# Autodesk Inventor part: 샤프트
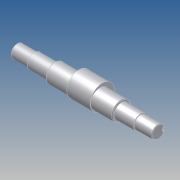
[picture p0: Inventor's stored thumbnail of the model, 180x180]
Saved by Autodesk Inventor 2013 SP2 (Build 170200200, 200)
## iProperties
Created: 2013-06
Part Number: 샤프트
Document SubType Name: Modeling
Designer: SeoGD™[esajin.kr]
Density: 1 g/cm^3
Material: 일반
Mass: 168.947 g
Surface Area: 248.524 cm^2
Volume: 168.947 cm^3
Author: SeoGD™[esajin.kr]
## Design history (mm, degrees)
sketch "스케치1"
  geometry: L1 (-20.5, -41.331)-(-20.5, 32.669) reference; L2 (7.5, -30.031)-(7.5, 21.369) reference; L3 (135.5, -30.331)-(135.5, 21.669) reference; L4 (121.5, 21.369)-(121.5, -30.031) reference; L5 (184.5, -4.331)-(-57.5, -4.331); L6 (184.5, -4.331)-(184.5, 6.669); L7 (154.5, 8.169)-(121.5, 8.169); L8 (121.5, 8.169)-(121.5, 11.669); L9 (121.5, 11.669)-(7.5, 11.669); L10 (7.5, 11.669)-(7.5, 8.169); L11 (7.5, 8.169)-(-27.5, 8.169); L12 (-27.5, 8.169)-(-27.5, 6.669); L13 (-27.5, 6.669)-(-57.5, 6.669); L14 (-57.5, 6.669)-(-57.5, -4.331); L15 (154.5, 8.169)-(154.5, 6.669); L16 (154.5, 6.669)-(184.5, 6.669); C1 r 32.5 at (64.5, -4.331) reference; 1 further point
  constraints: 24 end point, 8 perpendicular, 5 point on line, 3 parallel, 2 collinear
  dimensions: "d1" = 25 diameter of L11 L5; "d2" = 32 diameter of L9 L5; "d3" = 22 diameter of L13 L5; "d4" = 35 distance of L10.end L11.end; "d5" = 30 distance of L12.end L13.end; "d15" = 33 distance of L7.start L7.end; "d26" = 30 distance of L15.end L6.end
revolve "회전1" sketch "스케치1" stored, may be unused: angle "d6" = 90 deg
node "작업 평면1"
sketch "스케치2"
  geometry: C1 r 16 at (0, 0) reference; C2 r 16 at (0, 0) reference; C3 r 20.75 at (0, 4); C4 r 16 at (0, 0) reference; 1 further point
  constraints: 1 centre point, 1 vertical alignment
  dimensions: "d8" = 41.5 diameter of C3; "d25" = 4 distance of C3.centre C1.centre
extrude "돌출1" join sketch "스케치2" stored distance "d9" = 40; taper "d10" = 0 deg
chamfer "모따기1" distance "d11" = 1; stored, may be unused: second distance "d12" = 2, angle "d13" = 45 deg
node "작업 평면2"
sketch "스케치3"
  geometry: L1 (-15, -10)-(-15, 10) reference; L2 (-15, 3)-(0, 3); L3 (0, -3)-(-15, -3); A1 r 3 centre (0, 0) between (0, -3) and (0, 3); 2 further points
  constraints: 4 end point, 2 perpendicular, 2 point on circle, 2 point on line, 2 tangent, 1 centre point, 1 horizontal alignment, 1 midpoint
  dimensions: "d16" = 18 dimension on A1 L1; "d17" = 6 distance between parallel lines of L3 L2
extrude "돌출2" cut sketch "스케치3" distance "d18" = 3.5; taper "d19" = 0 deg
node "작업 평면3"
node "솔리드1"
mirror "대칭1"
node "참조1"
node "참조2"
node "참조3"
node "참조4"
node "참조5"
node "투영된 루프1"
